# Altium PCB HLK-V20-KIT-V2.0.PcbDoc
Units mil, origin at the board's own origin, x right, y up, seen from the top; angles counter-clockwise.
Board outline 1181.1 x 1102.36 mil, 2 copper layers (Top Layer, Bottom Layer); 17 components, 58 nets, 93 pads, 18 vias.
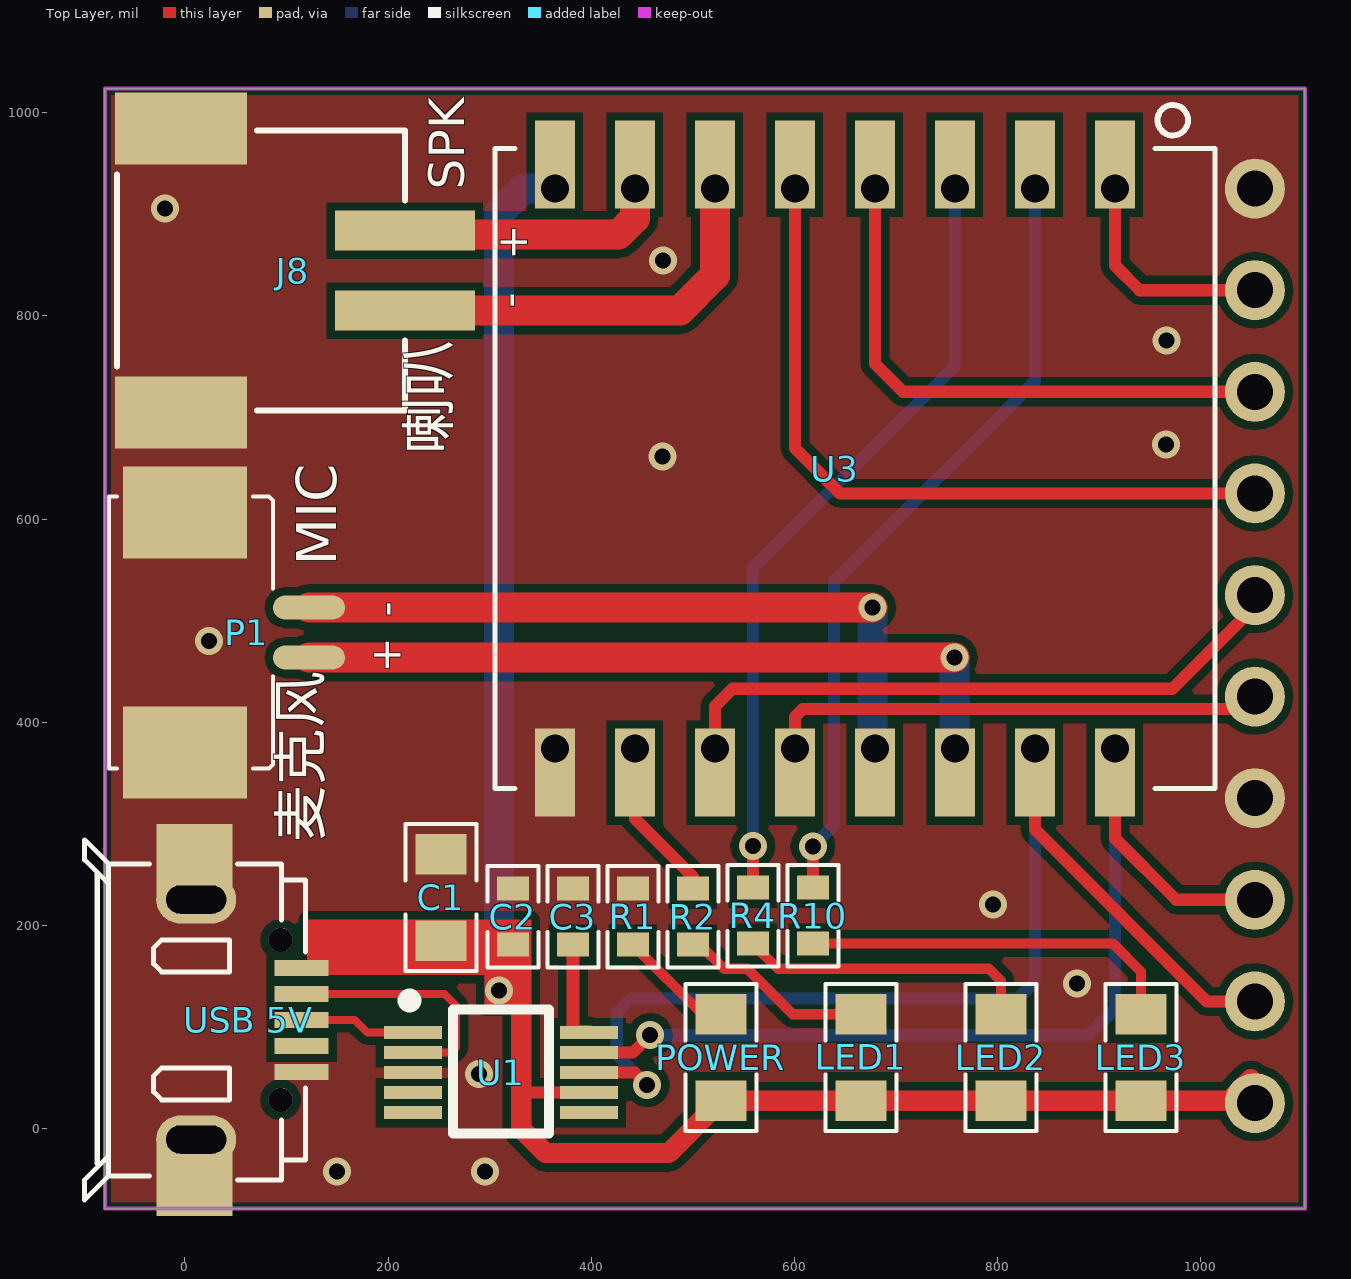
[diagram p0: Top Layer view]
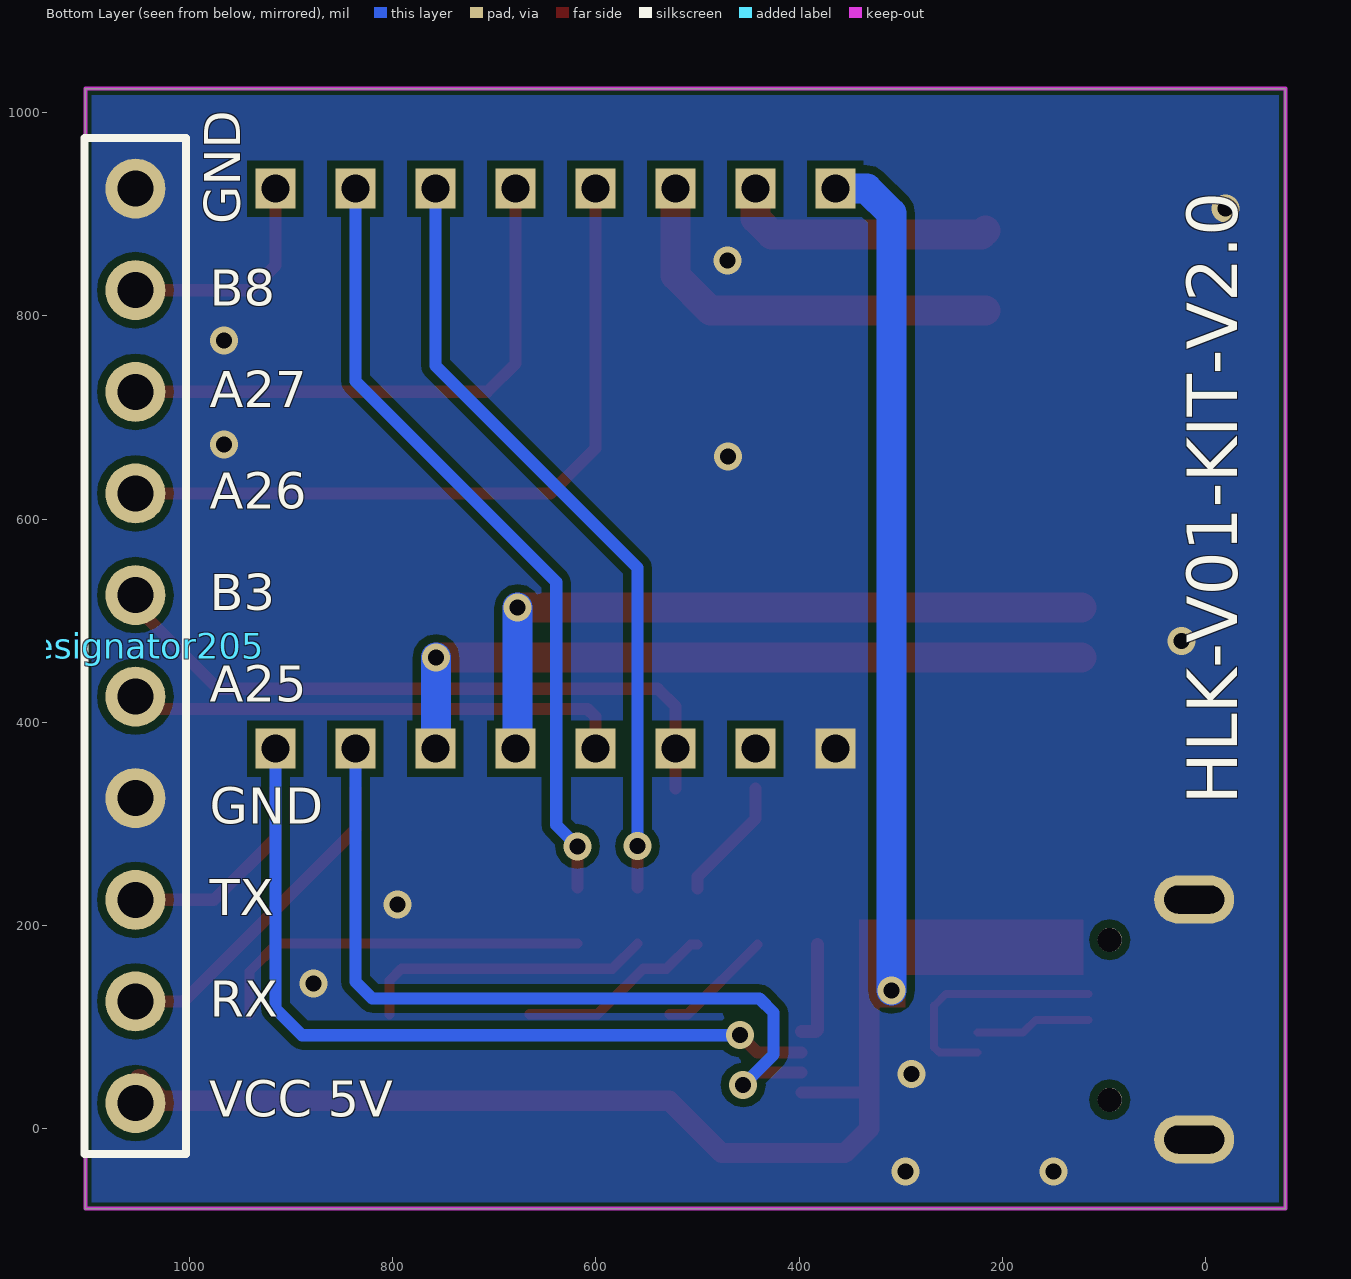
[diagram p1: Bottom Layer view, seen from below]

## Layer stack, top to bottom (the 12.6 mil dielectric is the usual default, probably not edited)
Top Solder: solder mask 0.4, Solder Resist, Dk 3.5
Top Layer: signal copper 1.4
Dielectric1: dielectric 12.6, FR-4, Dk 4.8
Bottom Layer: signal copper 1.4
Bottom Solder: solder mask 0.4, Solder Resist, Dk 3.5

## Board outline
-78.74,-78.74 -78.74,1023.62 1102.36,1023.62 1102.36,-78.74

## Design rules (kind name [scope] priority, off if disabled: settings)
Clearance Clearance_1 [OnLayer('Keep-Out Layer')] p1: gap=3.94
Clearance [All] p2: gap=7.87
FabricationTestpoint [(IsPad And (OnTopLayer Or OnBottomLayer))] p1: side=3 testpointundercomponent=TRUE minsize=40 maxsize=100 preferedsize=60 minholesize=0 maxholesize=40 preferedholesize=32 testpointgrid=1 allowsidetop=TRUE allowsidebottom=TRUE usegrid=TRUE gridtolerance=0.01
PlaneConnect [All] p1: planeconnectstyle=Direct reliefexpansion=20 reliefentries=4 reliefconductorwidth=10 reliefairgap=10
PolygonConnect [All] p1: connectstyle=Direct reliefconductorwidth=10 reliefentries=4 polygonreliefangle="90 Angle" airgapwidth=10
RoutingVias [All] p1: holewidth=15.75 width=27.56 viastyle="Through Hole" minholewidth=15.75 minwidth=27.56 maxholewidth=15.75 maxwidth=27.56
SolderMaskExpansion [All] p1: expansion=4
Width [All] p1: maxlimit=196.85 minlimit=7.09 preferedwidth=10
27 further rules are at their usual default settings.

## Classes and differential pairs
component class HLK-V01-KIT-V1.0: C1 C2 LED1 LED2 LED3 P1 POWER R1 R2 R4 R10 R11 "USB 5V"

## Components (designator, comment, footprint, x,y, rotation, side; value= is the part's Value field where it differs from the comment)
C1 "4.7UF" 0805R 251.97,270.04 r270 top
C2 "0.1UF" 0603 322.83,208.66 r270 top
C3 "0.1UF" 0603 381.89,208.66 r270 top
Designator205 "Comment" HDR1X10 1053.15,925.2 r270 bottom locked
J8 "SPK" PH2.0-2P 216.54,805.12 r90 top
LED1 "LED2" 0805R 665.35,27.56 r90 top
LED2 "LED2" 0805R 803.15,27.56 r90 top
LED3 "LED3" 0805R 940.94,27.56 r90 top
P1 "1*1.27mm" 1.25-2P 122.05,488.19 r90 top locked
POWER "LED" 0805R 527.56,27.56 r90 top
R1 "1K" 0603 440.94,208.66 r90 top
R2 "1K" 0603 500,208.66 r90 top
R4 "1K" 0603 559.06,209.66 r90 top
R10 "1K" 0603 618.11,209.66 r90 top
U1 "CH340E" MSOP-10 311.02,55.12 r270 top
U3 "Comment" HLK-V20 915.35,964.57 r270 top
"USB 5V" "USB" usb 7.87,106.3 r270 top locked (schematic designator USB1)

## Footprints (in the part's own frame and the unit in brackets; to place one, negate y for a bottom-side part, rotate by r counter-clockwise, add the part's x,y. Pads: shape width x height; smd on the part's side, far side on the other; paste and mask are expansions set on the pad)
1.25-2P [mm]
  oval 0.6x1.8 smd: 1(0.625,0) 2(-0.625,0)
  rect 2.3x3.1 smd: 3(-3,3.1) 4(3,3.1)
  silkscreen extent -3.4,0.9 3.4,5
0603 [mm]
  rect 0.6x0.8 smd: 1(-0.7,0) 2(0.7,0)
  silkscreen extent -1.27,-0.64 1.27,0.64
0805R [mil]
  rect 40x50 smd: 1(0,0) 2(85,0)
  silkscreen extent -30,-35 115,35, body extent 4,-25 83,25, height 22
HDR1X10 [mm]
  round 1.5 hole 0.9: 1(0,0) 2(2.54,0) 3(5.08,0) 4(7.62,0) 5(10.16,0) 6(12.7,0) 7(15.24,0) 8(17.78,0) 9(20.32,0) 10(22.86,0)
  silkscreen extent -1.27,-1.27 24.13,1.27
HLK-V20 [mm]
  rect 1.4x1 smd: 1(0,0) 2(0,-2) 3(0,-4) 4(0,-6) 5(0,-8) 6(0,-10) 7(0,-12) 8(0,-14) 9(16,-14) 10(16,-12) 11(16,-10) 12(16,-8) 13(16,-6) 14(16,-4) 15(16,-2) 16(16,0)
  rect 1x1 hole 0.7: 1(1,0) 2(1,-2) 3(1,-4) 4(1,-6) 5(1,-8) 6(1,-10) 7(1,-12) 8(1,-14) 9(15,-14) 10(15,-12) 11(15,-10) 12(15,-8) 13(15,-6) 14(15,-4) 15(15,-2) 16(15,0)
  silkscreen extent -1.09,-15.5 16,2.5
MSOP-10 [mm]
  rect 0.33x1.45 smd: 1(-1,-2.2) 2(-0.5,-2.2) 3(0,-2.2) 4(0.5,-2.2) 5(1,-2.2) 6(1,2.2) 7(0.5,2.2) 8(0,2.2) 9(-0.5,2.2) 10(-1,2.2)
  silkscreen extent -1.95,-2.44 1.53,1.2
PH2.0-2P [mm]
  rect 1x3.5 smd: 1(0,0) 2(2,0)
  rect 1.8x3.3 smd: 3(4.55,5.6) 4(-2.55,5.6)
  silkscreen extent -2.5,0 4.5,7.2
usb [mm]
  oval 1.2x2 hole 0.7 slot 1.5 at 90 deg: 1(-3.028,0.081) 1(2.972,0.081)
  rect 0.4x1.35 smd: 1(1.28,2.719) 2(0.63,2.719) 3(-0.02,2.719) 4(-0.67,2.719) 5(-1.32,2.719)
  round 0.6 hole 0.6: 6(1.98,2.194) 9(-2.02,2.194)
  rect 1.8x1.9 smd: 7(3.98,0.044) 8(-4.02,0.044)
  silkscreen extent -4.52,-2.71 4.48,2.82

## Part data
C1 C2 C3: library part CAP, "Capacitor"
LED1 LED2 LED3: library part LED
P1: library part Component_1
R1 R2 R4 R10: library part RES1
"USB 5V": library part USB-B

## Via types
v1: diameter 27.56, hole 15.75, Top Layer to Bottom Layer, tented both sides, 18 vias

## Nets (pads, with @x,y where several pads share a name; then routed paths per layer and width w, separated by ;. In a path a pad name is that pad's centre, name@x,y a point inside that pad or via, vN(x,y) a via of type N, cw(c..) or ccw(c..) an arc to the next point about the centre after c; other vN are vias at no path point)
3.3V: 
5V: "USB 5V.5" C1.2 C2.2 Designator205.10 LED1.1 LED2.1 LED3.1 POWER.1 U1.7 U3.8 | length 1947.6
  Top Layer w10: 333,54 333,164
  Top Layer w12: 333,35.43 U1.7
  Top Layer w20: C2.2 331,172.94 331,0 355,-24 476,-24 POWER.1 LED1.1 LED2.1 LED3.1 1027.95,27.56 Designator205.10@1049.21,48.82
  Bottom Layer w29.53: v1(309,136) 309,901 333.2,925.2 U3.8@364.17,925.2
ACE_N: 
ACE_P: 
CTS: U1.5
DM: "USB 5V.4" U1.2 | length 242.7
  Top Layer w7.87: 114.91,132.68 255.32,132.68 267,121 267,80 261.8,74.8 U1.2
DP: "USB 5V.3" U1.1 | length 114.7
  Top Layer w7.87: 114.91,107.09 166.91,107.09 179.51,94.49 U1.1
GND: "USB 5V.1" "USB 5V.7" "USB 5V.8" C1.1 C2.1 C3.1 Designator205.1 Designator205.7 J8.3 J8.4 P1.3 P1.4 R1.2 U1.3 U3.9
  other v1: 149.61,-42.22 295.28,-42.22 289.32,54 877.95,142.97 795.28,220.47 23.62,479.9 469.85,661.42 965.8,673.23 966.14,775.59 470.47,854.33 -19.69,905.51
IO9: 
IO10: 
IO11: 
MIC0_N: 
MIC0_P: 
MIC+: P1.2 U3.14 | length 725.1
  Top Layer w29.53: P1.2 v1(757.29,463.58)
  Bottom Layer w29.53: v1(757.29,463.58) 757.29,374.6 U3.14@757.87,374.02
MIC-: P1.1 U3.13 | length 694.6
  Top Layer w29.53: P1.1 v1(676.93,512.8)
  Bottom Layer w29.53: v1(676.93,512.8) 676.93,376.22 U3.13@679.13,374.02
NetC3_2: C3.2 U1.10 | length 100.3
  Top Layer w12.99: C3.2 381.89,97.11 383.33,95.67 U1.10@397.64,95.67
NetCHRX_1: 
NetCHTX_1: 
NetLED1_2: LED1.2 R2.1 | length 193.7
  Top Layer w10: R2.1 506.9,181.1 530.59,157.41 553.45,157.41 598.31,112.56 LED1.2
NetLED2_2: LED2.2 R4.1 | length 292.3
  Top Layer w10: R4.1 583.74,157.41 791.41,157.41 803.15,145.67 LED2.2
NetLED3_2: LED3.2 R10.1 | length 376.3
  Top Layer w10: R10.1 913.59,182.1 940.94,154.74 LED3.2
NetON/OFF_2: 
NetP1_1: 
NetP1_2: 
NetP2_1: 
NetP2_2: 
NetPOWER_2: POWER.2 R1.1 | length 115
  Top Layer w10: R1.1 509.49,112.56 POWER.2
NetR3_1: 
NetR10_2: 
NetR12_1: 
NetRST_2: 
PA_N: 
PA_P: 
PWM0: 
RTS: U1.4
RX0_CH340E: 
RXD: 
SIO0: 
SIO1: 
SPK+: J8.2 U3.7 | length 263.9
  Top Layer w29.53: J8.2 220.39,880 427,880 442.91,895.91 U3.7@442.91,925.2
SPK-: J8.1 U3.6 | length 405
  Top Layer w29.53: J8.1 487.12,805.12 521.65,839.65 U3.6@521.65,925.2
TCK/IO4: 
TDI/IO7: 
TDO/IO6: 
TMS/IO5: 
TX0_CH340E: 
TXD: 
UART_RX: Designator205.9 U1.8 U3.15 | length 1126.4
  Top Layer w12: U1.8 442.88,55.12 v1(455,43) ; U3.15@836.61,334.65 836.61,294.39 1005.8,125.2 Designator205.9
  Bottom Layer w12: v1(455,43) 425,73 425,114 439,128 820,128 836.61,144.61 U3.15@836.61,374.02
UART_TX: Designator205.8 U1.9 U3.16 | length 1003.4
  Top Layer w12: U1.9 440.8,74.8 v1(458,92) ; U3.16@915.35,334.65 915.35,285.65 975.8,225.2 Designator205.8
  Bottom Layer w12: v1(458,92) 889.24,92 915.35,118.11 U3.16@915.35,374.02
US_GPIO_B2: R2.2 U3.10 | length 122.1
  Top Layer w12: U3.10@442.91,334.65 442.91,305.09 500,248 R2.2
US_GPIO_B3: Designator205.5 U3.11 | length 664.3
  Top Layer w12: U3.11@521.65,334.65 521.65,415.65 539,433 972,433 1053.15,514.15 Designator205.5
US_GPIO_B6: R4.2 U3.3 | length 770.3
  Top Layer w12: R4.2 v1(559.06,277.94)
  Bottom Layer w12: v1(559.06,277.94) 559.06,552.06 757.87,750.87 U3.3@757.87,925.2
US_GPIO_B7: R10.2 U3.2 | length 778.5
  Top Layer w12: R10.2 v1(618.11,277.83)
  Bottom Layer w12: v1(618.11,277.83) 639,298.72 639,538 836.61,735.61 U3.2@836.61,925.2
US_GPIO_B8: Designator205.2 U3.1 | length 223.5
  Top Layer w12: U3.1@915.35,925.2 915.35,849.65 939.8,825.2 Designator205.2
US_SPIM_CLK: Designator205.4 U3.5 | length 726.7
  Top Layer w12: U3.5@600.39,925.2 600.39,669.61 644.8,625.2 Designator205.4
US_SPIM_MISO: Designator205.6 U3.12 | length 499.4
  Top Layer w12: U3.12@600.39,374.02 600.39,405.39 608.13,413.13 1053.15,413.13 Designator205.6
US_SPIM_MOSI: Designator205.3 U3.4 | length 557.8
  Top Layer w12: U3.4@679.13,925.2 679.13,752.87 706.8,725.2 Designator205.3
VMIC: 
pads on no net: "USB 5V.2" "USB 5V.6" "USB 5V.9" U1.6

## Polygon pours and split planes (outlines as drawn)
GND on Top Layer "MidLayer1-No Net" (solid, remove dead copper, pour order 4): -78.74,-78.74 1102.36,-78.74 1102.36,1023.62 -78.74,1023.62
GND on Bottom Layer "MidLayer1-No Net" (solid, remove dead copper, pour order 6): -78.74,-78.74 1102.36,-78.74 1102.36,1023.62 -78.74,1023.62

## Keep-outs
Keep-Out Layer:
  the board outline again, w3.94

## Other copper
Top Layer:
  rectangle net 5V: 295,119 341,151
  rectangle net 5V: 120,151 341,206

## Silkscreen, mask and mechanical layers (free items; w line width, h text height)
Top Overlay:
  text "+" at 311.02,889.76 h30 r270
  text "-" at 311.02,822.83 h30 r270
  text "喇叭" at 273,664 h70 r90
  text "MIC" at 149,554 h39.37 r90
  text "-" at 212.6,503.94 h30 r90
  text "+" at 212.6,448.82 h30 r90
  text "麦克风" at 147,282 h70 r90
Bottom Overlay:
  text "GND" at 950,890 h35.43 r270
  text "B8" at 980,810 h35.43
  text "A27" at 980,710 h35.43
  text "A26" at 980,610 h35.43
  text "B3" at 980,510 h35.43
  text "A25" at 980,420 h35.43
  text "HLK-V01-KIT-V2.0" at -31.5,318.9 h50 r270
  text "GND" at 980,300 h35.43
  text "TX" at 980,210 h35.43
  text "RX" at 980,110 h35.43
  text "VCC 5V" at 980.31,11.81 h35.43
